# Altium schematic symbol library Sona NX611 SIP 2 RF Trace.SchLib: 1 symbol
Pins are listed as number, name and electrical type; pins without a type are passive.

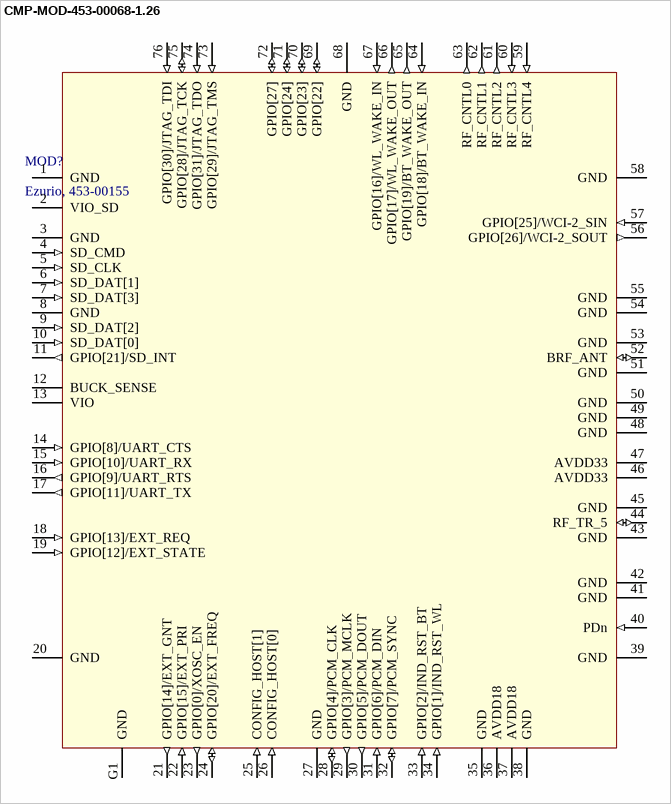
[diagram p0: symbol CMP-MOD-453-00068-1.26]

## CMP-MOD-453-00068-1.26
designator MOD?, comment Ezurio, 453-00155
MOD, Sona NX611  2 RF Trace SIP; Subpart Type: WiFi; Value: Laird, 453-00155; Substitutes Allowed: NO
footprint Laird, 453-00155 (Laird Sona NX611 SIP)
pins: 1 GND, 2 VIO_SD "Power", 3 GND (power) "Power", 4 SD_CMD (in) "I", 5 SD_CLK (in) "I", 6 SD_DAT[1] (in) "I", 7 SD_DAT[3] (in) "I", 8 GND "Do Not Connect", 9 SD_DAT[2] (in) "I", 10 SD_DAT[0] (in) "I", 11 GPIO[21]/SD_INT (out) "O", 12 BUCK_SENSE "Power", 13 VIO (power) "Power", 14 GPIO[8]/UART_CTS (in) "I", 15 GPIO[10]/UART_RX (in) "I", 16 GPIO[9]/UART_RTS (out) "O", 17 GPIO[11]/UART_TX (out) "O", 18 GPIO[13]/EXT_REQ (in) "I", 19 GPIO[12]/EXT_STATE (in) "I", 20 GND, 21 GPIO[14]/EXT_GNT (out) "O", 22 GPIO[15]/EXT_PRI (in) "I", 23 GPIO[0]/XOSC_EN (out) "O", 24 GPIO[20]/EXT_FREQ (io) "I/O", 25 CONFIG_HOST[1] (in) "I", 26 CONFIG_HOST[0] (in) "I", 27 GND (power) "Power", 28 GPIO[4]/PCM_CLK (io) "I/O (Master or Slave)", 29 GPIO[3]/PCM_MCLK (out) "O", 30 GPIO[5]/PCM_DOUT (out) "O", 31 GPIO[6]/PCM_DIN (in) "I", 32 GPIO[7]/PCM_SYNC (io) "I/O (Master or Slave)", 33 GPIO[2]/IND_RST_BT (in) "I", 34 GPIO[1]/IND_RST_WL (in) "I", 35 GND (power) "Power", 36 AVDD18 (power) "Power", 37 AVDD18 (power) "Power", 38 GND (power) "Power", 39 GND, 40 PDn (in) "I", 41 GND "Do Not Connect", 42 GND "Do Not Connect", 43 GND (power) "Power", 44 RF_TR_5 (io) "I/O", 45 GND (power) "Power", 46 AVDD33 (power) "I", 47  AVDD33, 48 GND (power) "Power", 49 GND "I/O", 50 GND (power) "Power", 51 GND (power), 52 BRF_ANT (io) "I/O", 53 GND (power) "Power", 54 GND "Power", 55 GND (power) "Power", 56 GPIO[26]/WCI-2_SOUT (out) "I", 57 GPIO[25]/WCI-2_SIN (in) "I", 58 GND, 59 RF_CNTL4 (in) "I", 60 RF_CNTL3 (in) "I", 61 RF_CNTL2 (out) "O", 62 RF_CNTL1 (out) "O", 63 RF_CNTL0 (out) "O", 64 GPIO[18]/BT_WAKE_IN (in) "I", 65 GPIO[19]/BT_WAKE_OUT (out) "O", 66 GPIO[17]/WL_WAKE_OUT (out) "O", 67 GPIO[16]/WL_WAKE_IN (in) "I", 68 GND (power) "Power", 69 GPIO[22] (io) "I/O", 70 GPIO[23] (io) "I/O", 71 GPIO[24] (io) "I/O", 72 GPIO[27] (io) "I/O", 73 GPIO[29]/JTAG_TMS (in) "I", 74 GPIO[31]/JTAG_TDO (in) "I", 75 GPIO[28]/JTAG_TCK (io) "I/O", 76 GPIO[30]/JTAG_TDI (in) "I", G1 GND (power) "Power"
